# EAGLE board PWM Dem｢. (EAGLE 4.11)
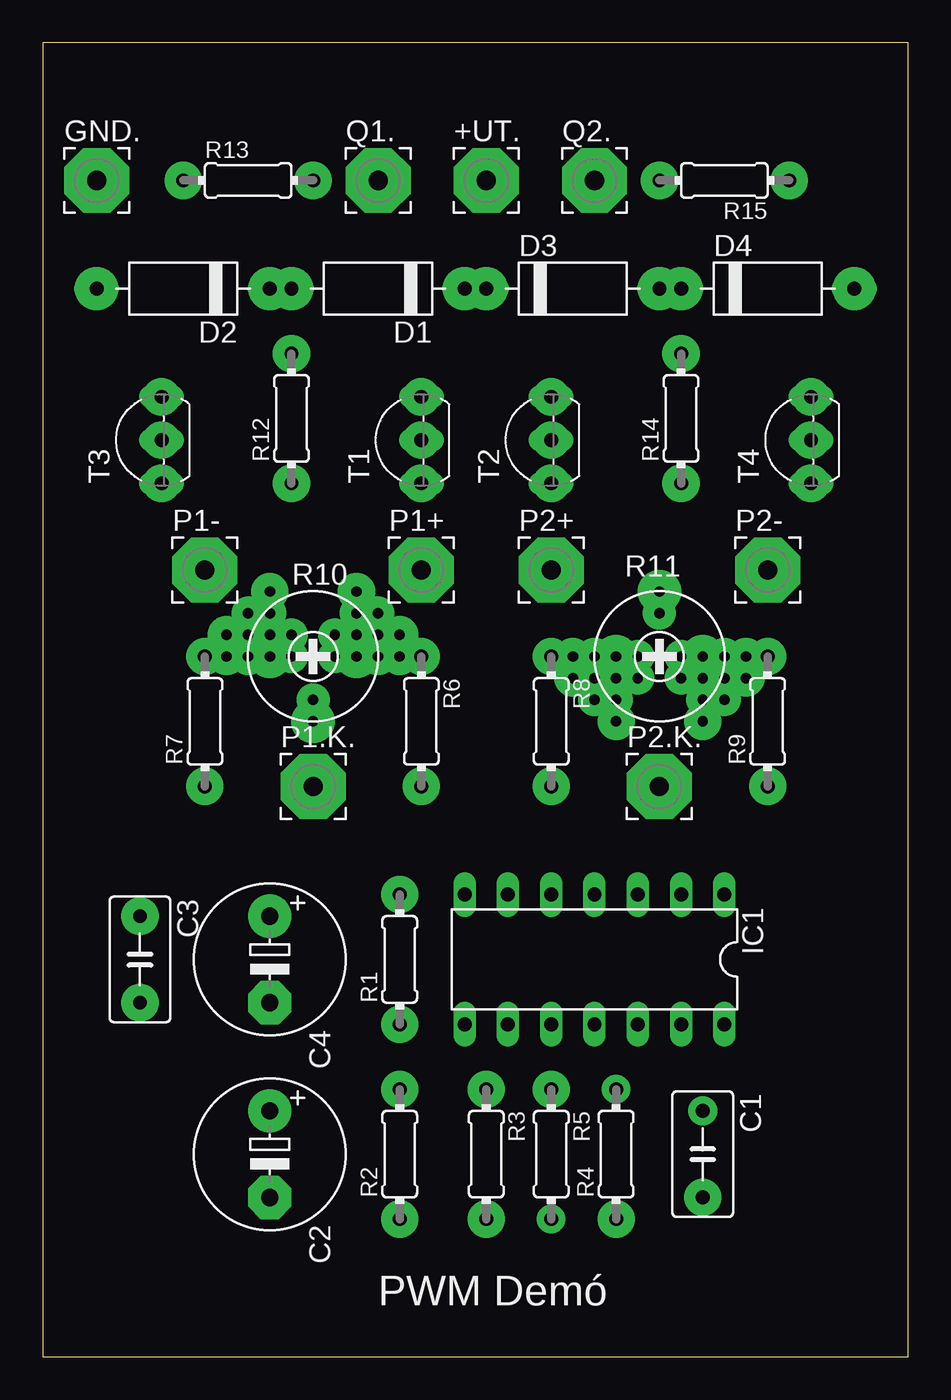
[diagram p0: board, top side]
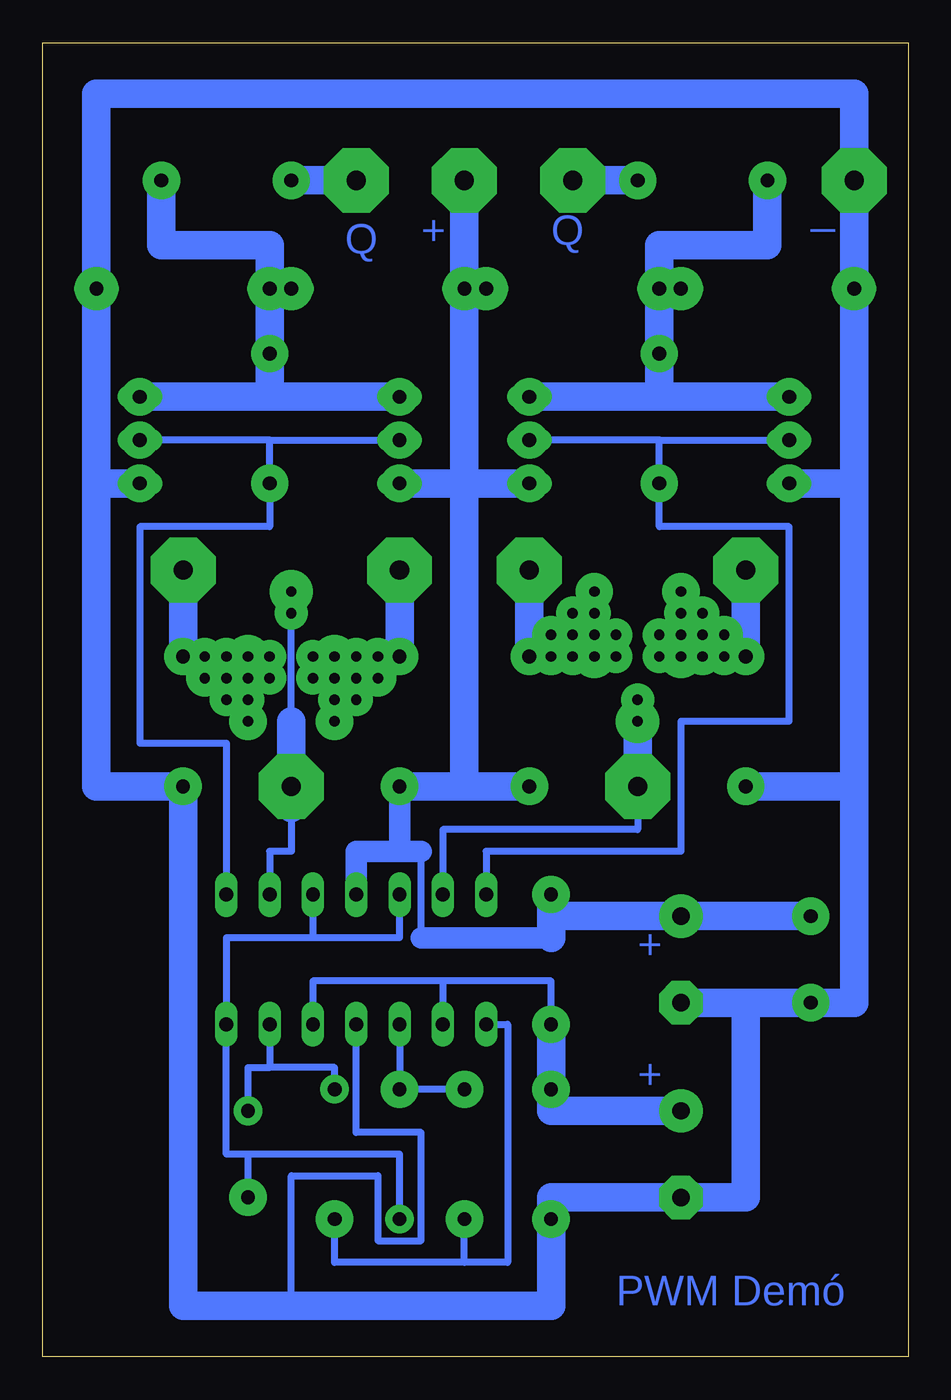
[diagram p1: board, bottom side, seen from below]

Size 50.78 x 77.14 mm. Coordinates in mm from the lower left corner, seen from the top.
Outline: 0,0 50.78,0 50.78,77.14 0,77.14 0,0
Copper layers (1*16): Top 0.035mm / dielectric 1.5mm / Bottom 0.035mm
Design rules "default": minimum track width 10mil, minimum drill 24mil, track to track 8mil, track to pad 8mil, pad to pad 8mil, via to via 8mil, smd to smd 8mil, copper to edge 40mil, drill to drill 8mil, minimum pad ring 10mil, minimum via ring 8mil, stop-mask expansion 4mil, vias tented up to drill 0mil, thermal gap 10mil

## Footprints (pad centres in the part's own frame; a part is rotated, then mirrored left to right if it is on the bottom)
3,81/1,1 = drill 1.118 pad 3.81 octagon: 1 0,0
C050-035X075 = drill 0.813 octagon: 1 -2.54,0; 2 2.54,0
E5-8,5 = drill 1.016 pad 2.54 round: + -2.54,0 | drill 1.016 pad 2.54 octagon: - 2.54,0
D-10 = drill 0.813 long: A 5.08,0; C -5.08,0
DIL14 = drill 0.813 long: 1 -7.62,-3.81; 2 -5.08,-3.81; 3 -2.54,-3.81; 4 0,-3.81; 5 2.54,-3.81; 6 5.08,-3.81; 7 7.62,-3.81; 8 7.62,3.81; 9 5.08,3.81; 10 2.54,3.81; 11 0,3.81; 12 -2.54,3.81; 13 -5.08,3.81; 14 -7.62,3.81
0204/7 = drill 0.813 octagon: 1 -3.81,0; 2 3.81,0
RTRIM3339P = drill 0.61 round: 1 -2.54,0; 2 0,-2.54; 3 2.54,0
TO92-EBC = drill 0.813 long: B 0,-1.27; C -2.54,-1.27; E 2.54,-1.27

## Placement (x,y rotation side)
+UT.  [3,81/1,1]  26.03,69.05 0 top
C1  10NF  [C050-035X075]  38.73,11.9 270 top
C2  10µF  [E5-8,5]  13.33,11.9 270 top
C3  100nF  [C050-035X075]  5.71,23.33 270 top
C4  100µF  [E5-8,5]  13.33,23.33 270 top
D1  [D-10]  19.68,62.7 180 top
D2  [D-10]  8.25,62.7 180 top
D3  [D-10]  31.11,62.7 0 top
D4  [D-10]  42.54,62.7 0 top
GND.  (-UT)  [3,81/1,1]  3.17,69.05 0 top
IC1  LM324N  [DIL14]  32.38,23.33 180 top
P1+  [3,81/1,1]  22.22,46.19 0 top
P1-  [3,81/1,1]  9.52,46.19 0 top
P1.K.  [3,81/1,1]  15.87,33.49 0 top
P2+  [3,81/1,1]  29.84,46.19 0 top
P2-  [3,81/1,1]  42.54,46.19 0 top
P2.K.  [3,81/1,1]  36.19,33.49 0 top
Q1.  [3,81/1,1]  19.68,69.05 0 top
Q2.  [3,81/1,1]  32.38,69.05 0 top
R1  100K  [0204/7]  20.95,23.33 90 top
R2  100K  [0204/7]  20.95,11.9 90 top
R3  100K  [0204/7]  26.03,11.9 270 top
R4  100K  [0204/7]  33.65,11.9 90 top
R5  47K  [0204/7]  29.84,11.9 270 top
R6  3.3K  [0204/7]  22.22,37.3 270 top
R7  3.3K  [0204/7]  9.52,37.3 90 top
R8  3.3K  [0204/7]  29.84,37.3 270 top
R9  3.3K  [0204/7]  42.54,37.3 90 top
R10  10K  [RTRIM3339P]  15.87,41.11 0 top
R11  10K  [RTRIM3339P]  36.19,41.11 180 top
R12  330R  [0204/7]  14.6,55.08 90 top
R13  330R  [0204/7]  12.06,69.05 0 top
R14  330R  [0204/7]  37.46,55.08 90 top
R15  330R  [0204/7]  40,69.05 180 top
T1  BC337  [TO92-EBC]  20.95,53.81 90 top
T2  BC337  [TO92-EBC]  28.57,53.81 90 top
T3  BC327  [TO92-EBC]  5.71,53.81 90 top
T4  BC327  [TO92-EBC]  43.81,53.81 90 top

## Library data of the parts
+UT. GND. P1+ P1- P1.K. P2+ P2- P2.K. Q1. Q2. = wirepad
C1-C4 R1-R15 = rcl
D1-D4 = diode
IC1 = linear
T1-T4 = transistor

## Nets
N$1: D1.A D2.C R12.2 R13.1 T1.E T3.E
N$2: D3.A D4.C R14.2 R15.1 T2.E T4.E
N$3: IC1.7 R12.1 T1.B T3.B
N$4: IC1.1 R14.1 T2.B T4.B
N$5: C2.+ IC1.9 IC1.12 R1.1 R2.2
N$6: IC1.10 R3.1 R5.1
N$7: IC1.8 R3.2 R4.1
N$8: C1.2 IC1.3 IC1.5 IC1.14 R5.2
N$9: C1.1 IC1.13 R4.2
N$10: Q1..1 R13.2
N$11: P1+.1 R6.1 R10.3
N$12: P1-.1 R7.2 R10.1
N$13: IC1.6 P1.K..1 R10.2
N$14: IC1.2 P2.K..1 R11.2
N$15: P2+.1 R8.1 R11.3
N$16: P2-.1 R9.2 R11.1
N$17: Q2..1 R15.2
N$75: +UT..1 C3.1 C4.+ D1.C D3.C IC1.4 R1.2 R6.2 R8.2 T1.C T2.C
N$76: C2.- C3.2 C4.- D2.A D4.A GND..1 IC1.11 R2.1 R7.1 R9.1 T3.C T4.C

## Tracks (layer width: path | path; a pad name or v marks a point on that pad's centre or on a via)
N$1  (via drill 0.61 pad 2.18, 0.61 pad 2.54)
  Bottom 1.676: 14.6,56.35 T1.E | 14.6,56.35 R12.2 D1.A | T3.E 14.6,56.35 | 14.6,56.35 D1.A | D1.A 14.6,65.24 8.25,65.24 R13.1 | D1.A D2.C
  other vias: 14.6,58.89 14.6,62.7
N$2  (via drill 0.61 pad 2.18, 0.61 pad 2.54)
  Bottom 1.676: T4.E 37.46,56.35 | R14.2 D4.C | D4.C 37.46,65.24 43.81,65.24 R15.1 | T2.E 37.46,56.35 | 37.46,56.35 R14.2 | R14.2 D4.C | D4.C D3.A
  other vias: 37.46,58.89 43.81,69.05 37.46,62.7
N$3  (via drill 0.61 pad 2.18)
  Bottom 0.406: 14.6,53.81 R12.1 14.6,48.73 6.98,48.73 6.98,37.3 13.33,37.3 13.33,29.68 24.76,29.68 IC1.7 | 14.6,53.81 T3.B | 14.6,53.81 T1.B
  other vias: 14.6,51.27
N$4
  Bottom 0.406: 37.46,53.81 R14.1 37.46,48.73 45.08,48.73 45.08,36.03 40,36.03 IC1.1 | 37.46,53.81 T2.B | 37.46,53.81 T4.B
N$5  (via drill 0.61 pad 2.18)
  Bottom 0.406: IC1.12 34.92,22.06 27.3,22.06 | 27.3,22.06 IC1.9 | 27.3,22.06 20.95,22.06 R1.1
  Bottom 1.676: R1.1 R2.2 20.95,14.44 C2.+
  other vias: 20.95,15.71
N$6  (via drill 0.61 pad 2.18)
  Bottom 0.406: R3.1 R5.1 IC1.10
  other vias: 29.84,15.71 26.03,15.71
N$7
  Bottom 0.406: 26.03,5.55 23.49,5.55 23.49,19.52 IC1.8 | 26.03,5.55 R3.2 | 26.03,5.55 33.65,5.55 R4.1
N$8
  Bottom 0.406: R5.2 29.84,11.9 38.73,11.9 | 38.73,11.9 C1.2 | 38.73,11.9 40,11.9 IC1.14 40,24.6 34.92,24.6 | IC1.5 29.84,24.6 34.92,24.6 | IC1.3 34.92,24.6
N$9
  Bottom 0.406: R4.2 33.65,16.98 37.46,16.98 | C1.1 38.73,16.98 37.46,16.98 | IC1.13 37.46,16.98
N$10
  Bottom 1.676: R13.2 Q1..1
N$11  (via drill 0.61 pad 2.18, 0.61 pad 2.54)
  Bottom 1.676: v19.68,41.11 R10.3 v19.68,41.11 | v19.68,41.11 R6.1 | R6.1 P1+.1 | v19.68,41.11 R6.1
  other vias: 18.41,41.11 22.22,41.11
N$12  (via drill 0.61 pad 2.18, 0.61 pad 2.54)
  Bottom 1.676: R7.2 v10.79,41.11 | v10.79,41.11 v12.06,41.11 | v12.06,41.11 R10.1 | R7.2 v10.79,41.11 | v10.79,41.11 v12.06,41.11 | v12.06,41.11 R10.1 | R10.1 v12.06,41.11 | v12.06,41.11 v10.79,41.11 | v10.79,41.11 R7.2 | R7.2 P1-.1
  other vias: 13.33,41.11
N$13  (via drill 0.61 pad 2.54)
  Bottom 0.406: 15.87,34.76 P1.K..1 15.87,30.95 27.3,30.95 IC1.6 | v15.87,37.3 R10.2
  Bottom 1.676: P1.K..1 R10.2
N$14  (via drill 0.61 pad 1.93)
  Bottom 0.406: R11.2 36.19,37.3 P2.K..1 36.19,32.22 36.19,29.68 37.46,29.68 IC1.2
  Bottom 1.676: 36.19,32.22 36.19,37.3
  other vias: 36.19,43.65
N$15  (via drill 0.61 pad 2.18)
  Bottom 1.676: P2+.1 R8.1 v31.11,41.11 v32.38,41.11 R11.3
N$16  (via drill 0.61 pad 2.18)
  Bottom 1.676: P2-.1 R9.2 v41.27,41.11 v40,41.11 R11.1
N$17
  Bottom 1.676: R15.2 Q2..1
N$18  (via drill 0.61 pad 2.54)
  other vias: 18.41,41.11
N$19  (via drill 0.61 pad 2.54)
  other vias: 13.33,41.11
N$20  (via drill 0.61 pad 2.54)
  other vias: 38.73,41.11
N$21  (via drill 0.61 pad 2.54)
  other vias: 33.65,41.11
N$22  (via drill 0.61 pad 2.54)
  other vias: 36.19,44.92
N$23  (via drill 0.61 pad 2.54)
  other vias: 15.87,37.3
N$24  (via drill 0.61 pad 1.93)
  other vias: 15.87,38.57
N$25  (via drill 0.61 pad 1.93)
  other vias: 17.14,41.11
N$26  (via drill 0.61 pad 1.93)
  other vias: 14.6,41.11
N$27  (via drill 0.61 pad 1.93)
  other vias: 17.14,42.38
N$28  (via drill 0.61 pad 1.93)
  other vias: 18.41,42.38
N$29  (via drill 0.61 pad 1.93)
  other vias: 14.6,42.38
N$30  (via drill 0.61 pad 1.93)
  other vias: 13.33,42.38
N$31  (via drill 0.61 pad 1.93)
  other vias: 37.46,41.11
N$32  (via drill 0.61 pad 1.93)
  other vias: 34.92,41.11
N$33  (via drill 0.61 pad 1.93)
  other vias: 34.92,39.84
N$34  (via drill 0.61 pad 1.93)
  other vias: 33.65,39.84
N$35  (via drill 0.61 pad 1.93)
  other vias: 37.46,39.84
N$36  (via drill 0.61 pad 1.93)
  other vias: 38.73,39.84
N$37  (via drill 0.61 pad 1.93)
  other vias: 12.06,43.65
N$38  (via drill 0.61 pad 1.93)
  other vias: 13.33,43.65
N$39  (via drill 0.61 pad 1.93)
  other vias: 19.68,43.65
N$40  (via drill 0.61 pad 1.93)
  other vias: 18.41,43.65
N$41  (via drill 0.61 pad 1.93)
  other vias: 40,38.57
N$42  (via drill 0.61 pad 1.93)
  other vias: 38.73,38.57
N$43  (via drill 0.61 pad 1.93)
  other vias: 33.65,38.57
N$44  (via drill 0.61 pad 1.93)
  other vias: 32.38,38.57
N$45  (via drill 0.61 pad 1.93)
  other vias: 40,39.84
N$46  (via drill 0.61 pad 1.93)
  other vias: 32.38,39.84
N$47  (via drill 0.61 pad 1.93)
  other vias: 19.68,42.38
N$48  (via drill 0.61 pad 1.93)
  other vias: 12.06,42.38
N$49  (via drill 0.61 pad 2.18)
  other vias: 20.95,27.14
N$50  (via drill 0.61 pad 2.18)
  other vias: 20.95,19.52 20.95,8.09
N$51  (via drill 0.61 pad 2.18)
  other vias: 20.95,27.14 5.71,20.79
N$52  (via drill 0.61 pad 2.18)
  other vias: 38.73,9.36
N$53  (via drill 0.61 pad 2.18)
  other vias: 6.98,56.35
N$54  (via drill 0.61 pad 2.18)
  other vias: 33.65,8.09
N$55  (via drill 0.61 pad 1.68)
  other vias: 29.84,8.09 33.65,15.71
N$56  (via drill 0.61 pad 2.18)
  other vias: 26.03,8.09
N$57  (via drill 0.61 pad 2.18)
  other vias: 5.71,25.87
N$58  (via drill 0.61 pad 2.18)
  other vias: 9.52,33.49
N$59  (via drill 0.61 pad 2.18)
  other vias: 20.95,41.11
N$60  (via drill 0.61 pad 2.18)
  other vias: 29.84,41.11 22.22,33.49 9.52,41.11 42.54,33.49 42.54,41.11 29.84,33.49
N$61  (via drill 0.61 pad 2.18)
  other vias: 8.25,69.05
N$62  (via drill 0.61 pad 2.18)
  other vias: 15.87,69.05
N$63  (via drill 0.61 pad 2.18)
  other vias: 37.46,51.27
N$64  (via drill 0.61 pad 2.18)
  other vias: 36.19,69.05
N$65  (via drill 0.61 pad 2.18)
  other vias: 20.95,42.38
N$66  (via drill 0.61 pad 2.18)
  other vias: 10.79,42.38
N$67  (via drill 0.61 pad 2.18)
  other vias: 31.11,39.84
N$68  (via drill 0.61 pad 2.18)
  other vias: 41.27,39.84
N$69  (via drill 0.61 pad 2.18)
  other vias: 38.73,37.3
N$70  (via drill 0.61 pad 2.18)
  other vias: 33.65,37.3
N$71  (via drill 0.61 pad 2.18)
  other vias: 18.41,44.92
N$72  (via drill 0.61 pad 2.18)
  other vias: 13.33,44.92
N$73  (via drill 0.61 pad 1.68)
  other vias: 38.73,14.44
N$74  (via drill 0.61 pad 2.18)
  other vias: 6.98,53.81
N$75  (via drill 0.61 pad 2.18, 0.61 pad 2.54)
  Bottom 0.406: 28.57,24.6 28.57,29.68
  Bottom 1.27: 29.84,29.68 R8.2 | 29.84,29.68 32.38,29.68 IC1.4 | 28.57,29.68 29.84,29.68 | 20.95,24.6 28.57,24.6
  Bottom 1.676: D3.C +UT..1 | C3.1 C4.+ 20.95,25.87 R1.2 20.95,24.6 | D3.C D1.C D3.C | 26.03,51.27 D3.C | 26.03,51.27 T1.C T2.C 26.03,51.27 | 26.03,33.49 26.03,51.27 | R6.2 26.03,33.49 | 26.03,33.49 R8.2
  other vias: 5.71,25.87 26.03,62.7
N$76  (via drill 0.61 pad 2.18, 0.61 pad 2.54)
  Bottom 0.406: IC1.11 32.38,13.17 28.57,13.17 28.57,6.82 31.11,6.82 31.11,10.63 36.19,10.63 36.19,3.01
  Bottom 1.676: 9.52,20.79 C3.2 3.17,20.79 3.17,33.49 | 20.95,3.01 R2.1 | 20.95,3.01 36.19,3.01 42.54,3.01 R9.1 47.62,33.49 47.62,51.27 | 20.95,3.01 20.95,9.36 C2.- 9.52,9.36 9.52,20.79 | 3.17,51.27 D2.A GND..1 3.17,74.13 47.62,74.13 D4.A 47.62,51.27 | 3.17,51.27 T3.C | 3.17,33.49 R7.1 | 3.17,33.49 3.17,51.27 | 9.52,20.79 C4.- | 47.62,51.27 T4.C
  other vias: 6.98,51.27 6.98,51.27 45.08,51.27 9.52,33.49 42.54,33.49 6.98,51.27 3.17,62.7 47.62,62.7
N$77  (via drill 0.61 pad 2.18)
  other vias: 22.22,56.35
N$78  (via drill 0.61 pad 2.18)
  other vias: 22.22,53.81
N$79  (via drill 0.61 pad 2.18)
  other vias: 22.22,51.27
N$80  (via drill 0.61 pad 2.18)
  other vias: 29.84,51.27
N$81  (via drill 0.61 pad 2.18)
  other vias: 29.84,53.81
N$82  (via drill 0.61 pad 2.18)
  other vias: 29.84,56.35
N$83  (via drill 0.61 pad 2.18)
  other vias: 45.08,56.35
N$84  (via drill 0.61 pad 2.18)
  other vias: 45.08,53.81
N$85  (via drill 0.61 pad 2.18)
  other vias: 45.08,51.27
N$86  (via drill 0.61 pad 2.54)
  other vias: 13.33,62.7
N$87  (via drill 0.61 pad 2.54)
  other vias: 24.76,62.7
N$88  (via drill 0.61 pad 2.54)
  other vias: 36.19,62.7

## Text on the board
Bottom: _ | Q | Q | + | + | + | PWM Demó
tPlace: PWM Demó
